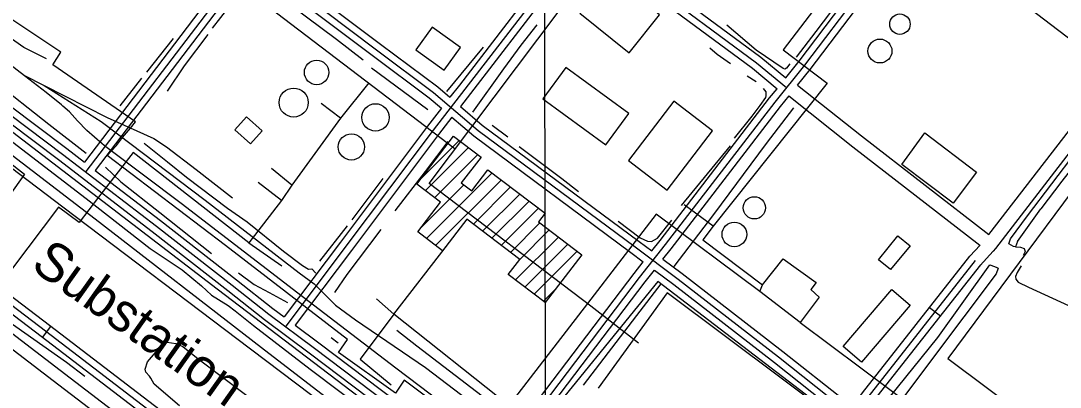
# Model space of a CAD drawing. Extents: x 3324104 to 3361979, y 612876 to 638273.
# Drawn here: x 3353376 to 3355626, y 633414 to 634208 of the extents above; entities that cross this region are included whole.
import ezdxf

# ---------------------------------------------------------------- set-up
doc = ezdxf.new("R2010")
doc.units = 0
for name, color, linetype in [('V-BLDG-OTLN', 7, 'Continuous'), ('V-DOMW-TANK', 7, 'Continuous'), ('V-GRID-MAJR', 7, 'Continuous'), ('V-RAIL-TRAK', 7, 'Continuous'), ('V-ROAD-CNTR', 7, 'Continuous'), ('V-SITE-OTLN', 7, 'Continuous'), ('V-SITE-OTLN-IDEN', 7, 'Continuous'), ('V-TOPO-SHOR', 7, 'Continuous'), ('V-UTIL-LINE', 7, 'Continuous')]:
    doc.layers.add(name, color=color, linetype=linetype)

msp = doc.modelspace()

# ---------------------------------------------------------------- linework, layer by layer
at = {"layer": 'V-BLDG-OTLN'}
for p, q in [((3354242.89947667, 633866.419240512), (3354325.0333124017, 633948.5530762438)), ((3354251.89945867, 633840.0632932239), (3354345.095272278, 633933.2601068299)), ((3354271.961418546, 633824.7703238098), (3354365.158232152, 633917.9671374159)), ((3354254.0074544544, 633736.1055011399), (3354396.202170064, 633878.3002167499)), ((3354242.7454769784, 633760.1994529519), (3354334.8252928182, 633852.2792687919)), ((3354274.0684143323, 633720.811531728), (3354416.26412994, 633863.007247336)), ((3354355.7272510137, 633767.1154391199), (3354436.326089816, 633847.714277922)), ((3354375.790210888, 633751.8224697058), (3354456.3880496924, 633832.4203085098)), ((3354395.852170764, 633736.5295002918), (3354476.450009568, 633817.1273390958)), ((3354415.915130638, 633721.237530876), (3354496.5119694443, 633801.8333696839)), ((3354435.9770905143, 633705.9445614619), (3354499.897962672, 633769.8644336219)), ((3354446.998068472, 633646.2546808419), (3354540.0198824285, 633739.2764947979)), ((3354455.94905057, 633690.5605922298), (3354518.711925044, 633753.3234667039)), ((3354467.060028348, 633630.9607114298), (3354560.0808423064, 633723.9825253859)), ((3354487.120988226, 633615.666742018), (3354580.1418021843, 633708.687555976)), ((3354507.1829481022, 633600.373772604), (3354533.405895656, 633626.5967201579))]:
    msp.add_line(p, q, dxfattribs=at)
for points in [[(3354586.5087894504, 634224.4325244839), (3354692.716577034, 634138.5826961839), (3354758.9704445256, 634220.547532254), (3354726.67850911, 634246.6494800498), (3354710.354541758, 634226.4545204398), (3354636.43868959, 634286.202400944)], [(3354231.018500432, 634144.7856837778), (3354292.5573773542, 634100.3837725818), (3354328.1203062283, 634149.671674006), (3354266.581429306, 634194.073585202)], [(3354692.0065784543, 634006.9889593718), (3354555.704851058, 634106.506760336), (3354506.204950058, 634038.7098959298), (3354642.506677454, 633939.192094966)], [(3354789.6713831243, 634033.366906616), (3354691.5335794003, 633905.258162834), (3354775.4344115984, 633840.98529138), (3354873.5732153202, 633969.0930351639)], [(3353864.7962328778, 634000.0049733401), (3353898.827164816, 633969.5720342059), (3353873.372215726, 633941.1080911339), (3353839.341283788, 633971.5420302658)], [(3355333.213, 633965.319), (3355444.8910000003, 633879.926), (3355394.647, 633812.77), (3355282.9620000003, 633896.7440000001)], [(3354456.0400503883, 633690.6515920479), (3354341.6012792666, 633777.883417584), (3354289.265383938, 633709.2265548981), (3354235.268491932, 633750.39047257), (3354284.61439324, 633815.124343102), (3354233.5004954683, 633854.089265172), (3354312.686337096, 633957.9650574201), (3354372.2832179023, 633912.53514828), (3354329.4663035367, 633856.363260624), (3354352.1622581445, 633839.0652952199), (3354387.2651879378, 633885.1132031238), (3354511.1399401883, 633790.6823919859), (3354496.971968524, 633772.0954291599), (3354590.1627821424, 633701.048571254), (3354511.124940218, 633597.3687786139), (3354431.311099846, 633658.2126569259)], [(3355232.323497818, 633690.158593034), (3355274.7144130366, 633741.798489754), (3355300.906360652, 633720.2975327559), (3355258.515445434, 633668.6576360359)], [(3355156.3836496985, 633502.3249687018), (3355261.846438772, 633625.56572222), (3355301.46235954, 633591.664790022), (3355195.999570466, 633468.424036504)]]:
    msp.add_lwpolyline(points, close=True, dxfattribs=at)
at = {"layer": 'V-DOMW-TANK'}
for centre, radius in [((3355279.0424043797, 634200.431572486), 22.136075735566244), ((3355235.8134908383, 634142.1696890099), 25.88489908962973), ((3354016.461929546, 634095.8497816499), 26.518120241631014), ((3353966.7360289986, 634030.5609122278), 31.449801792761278), ((3354143.8516747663, 633998.4999763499), 29.608969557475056), ((3354091.655779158, 633934.5241043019), 28.394865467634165), ((3354963.9790345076, 633802.628368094), 24.055551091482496), ((3354920.733121, 633744.9434834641), 26.720395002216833)]:
    msp.add_circle(centre, radius, dxfattribs=at)
at = {"layer": 'V-GRID-MAJR'}
msp.add_spline([(3354542.616, 618302.879), (3354530.278, 624362.207), (3354517.935, 630423.471), (3354505.593, 636484.758), (3354505.589, 636486.671)], degree=3, dxfattribs=at)
at = {"layer": 'V-RAIL-TRAK'}
for points in [[(3355824.3854434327, 634031.6344997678), (3355686.1738913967, 634137.7885225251), (3355480.9511141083, 634295.2301773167), (3355259.159114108, 634467.1391773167), (3355022.1207848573, 634648.9039759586), (3354854.770784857, 634777.0059759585), (3354747.4785265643, 634863.6636388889)], [(3354994.8000000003, 632277.343), (3354794.9390000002, 632430.505), (3354624.3740000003, 632561.778), (3354457.47, 632688.731), (3354410.4620000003, 632724.4890000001), (3354061.745, 632990.547), (3353708.9080000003, 633260.785), (3353584.803, 633355.677), (3353460.9620000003, 633450.366), (3353377.392, 633514.268), (3353092.648, 633732.826), (3352746.663, 633994.024), (3352512.14, 634175.561)], [(3352502.281, 634151.4230000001), (3352718.933, 633985.234), (3353086.217, 633704.517), (3353445.93, 633428.696), (3353715.359, 633222.774), (3353877.179, 633099.0970000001), (3354311.872, 632767.399), (3354334.588, 632752.709), (3354370.41, 632733.081), (3354457.47, 632688.731)], [(3354416.676, 633282.131), (3354188.215, 633455.425), (3353997.444, 633601.005), (3353984.9990000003, 633610.501), (3353723.356, 633812.084), (3353562.793, 633932.774), (3353552.002, 633940.885), (3353518.825, 633969.843), (3353498.943, 633990.6900000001), (3353481.721, 634010.183), (3353467.123, 634022.977), (3353464.073, 634025.5), (3353431.279, 634052.621), (3353384.123, 634088.359), (3353294.472, 634157.131)], [(3353382.424, 634089.664), (3353426.4020000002, 634067.435), (3353563.399, 633998.1900000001), (3353599.737, 633981.593), (3353627.295, 633969.008), (3353663.9050000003, 633952.712), (3353691.819, 633934.478), (3353755.575, 633885.931), (3353834.591, 633823.915)], [(3353426.4020000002, 634067.435), (3353550.046, 633989.735), (3353585.184, 633963.109), (3353775.187, 633819.137), (3353978.3880000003, 633662.058), (3354010.932, 633637.779), (3354020.732, 633628.386), (3354022.87, 633626.338), (3354057.346, 633592.028), (3354100.518, 633559.66), (3354252.0270000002, 633457.049), (3354436.648, 633316.13), (3354461.312, 633298.3470000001), (3354544.2660000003, 633238.5480000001), (3354564.187, 633223.042), (3354595.348, 633192.095), (3354655.018, 633132.893), (3354758.501, 633037.979), (3354838.068, 632959.931)], [(3354564.187, 633223.042), (3354499.233, 633290.296), (3354472.838, 633314.373), (3354440.191, 633344.153), (3354375.116, 633394.712), (3354233.661, 633502.5920000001), (3354189.8370000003, 633536.97)]]:
    msp.add_lwpolyline(points, dxfattribs=at)
at = {"layer": 'V-ROAD-CNTR'}
for p, q in [((3355343.1362761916, 633586.8577996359), (3355366.7352289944, 633568.3358366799)), ((3353422.7371169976, 633521.851929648), (3353440.9710805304, 633545.674882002))]:
    msp.add_line(p, q, dxfattribs=at)
for points in [[(3354182.121598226, 635746.1754809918), (3354018.760924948, 635537.3738985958), (3353982.41499764, 635481.0590112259), (3353715.4525315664, 635137.384698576), (3353649.706663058, 635051.1208711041), (3353421.915118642, 634750.8874715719), (3353365.78123091, 634675.6806219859), (3353063.8368348, 634284.0654052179), (3353055.92685062, 634262.7614478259), (3353056.6008492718, 634240.7944917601), (3353063.735835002, 634227.010519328), (3353091.9487785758, 634201.375570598), (3353466.5300294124, 633919.044135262), (3353669.547623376, 633763.143447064), (3353833.526295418, 633634.9757033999), (3353912.8701367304, 633572.257828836), (3354012.1179382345, 633498.229976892), (3354351.653259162, 633241.672490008), (3354431.0831003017, 633183.7016059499)], [(3354917.5051274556, 635717.3555386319), (3354668.8916246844, 635401.78716977), (3354512.4139376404, 635194.9325834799), (3354439.7530829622, 635096.420780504), (3354190.9995804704, 634777.8394176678), (3354117.5367273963, 634667.7306378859), (3353901.947158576, 634388.4701964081), (3353826.343309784, 634287.785397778), (3353516.7949288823, 633881.1582110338)], [(3353157.175648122, 635499.8729735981), (3353361.4352396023, 635334.13230508), (3353496.1649701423, 635235.156503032), (3353653.2386559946, 635113.25774683), (3353743.9004746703, 635047.529878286), (3353963.8420347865, 634886.9411994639), (3354117.5197274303, 634758.8044557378), (3354217.67952711, 634681.4496104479), (3354563.3308358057, 634421.7231299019), (3354647.9136666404, 634354.1892649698), (3354968.927024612, 634116.7357398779), (3355033.3788957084, 634063.260846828)], [(3354385.4241916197, 633216.154541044), (3354715.5335314, 633651.388670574), (3354771.896418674, 633722.899527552), (3355008.8109448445, 634031.2819107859), (3355072.8958166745, 634111.3617506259), (3355314.1163342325, 634430.291112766), (3355383.1521961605, 634526.260920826), (3355497.399967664, 634672.4536284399), (3355562.5108374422, 634771.8904295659), (3355642.2276780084, 634881.8442096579), (3355704.899552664, 634943.827085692), (3355851.978258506, 635128.869715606)], [(3352892.758176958, 635096.3707806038), (3352992.815976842, 635041.151891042), (3353182.5515973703, 634895.7211819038), (3353354.5072534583, 634748.9354754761), (3353438.82608482, 634686.254600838), (3353843.7952748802, 634371.5262302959), (3353920.754120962, 634314.868343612), (3354145.726671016, 634144.94468346), (3354269.488423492, 634052.6908679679), (3354365.761230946, 633970.008033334), (3354705.6285512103, 633717.741537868), (3354798.8313648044, 633648.3896765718), (3355016.481929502, 633479.5140143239), (3355149.9176626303, 633373.670226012), (3355228.120506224, 633317.9763373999), (3355464.206034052, 633129.06671522), (3355577.790806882, 633036.615900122)], [(3354918.7771249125, 634809.9303534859), (3354629.5387033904, 634443.890085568), (3354559.5568433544, 634348.5852761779), (3354337.55928735, 634059.4078545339), (3354268.538425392, 633970.497032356), (3354079.862802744, 633719.2585348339), (3353948.3830657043, 633544.18588498)], [(3353375.9132106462, 634714.3325446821), (3353353.8302548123, 634684.746603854), (3353050.567861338, 634291.4213905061), (3353040.843880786, 634265.2334428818), (3353041.712879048, 634236.926499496), (3353051.6538591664, 634217.721537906), (3353082.3707977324, 634189.8115937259), (3353457.448047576, 633907.106159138), (3353660.3606417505, 633751.2854707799), (3353824.256313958, 633623.1827269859), (3353903.733155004, 633560.3598526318), (3354003.1119562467, 633486.2340008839), (3354342.70927705, 633229.6295140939), (3354422.240117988, 633171.5856301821)], [(3353399.9891624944, 634696.434580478), (3353377.7322070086, 634666.6146401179), (3353077.105808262, 634276.70941993), (3353071.0098204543, 634260.28945277), (3353071.4888194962, 634244.6624840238), (3353075.8178108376, 634236.2995007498), (3353101.5267594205, 634212.9395474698), (3353475.6120112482, 633930.9821113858), (3353513.6419351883, 633901.779169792)], [(3355031.82289882, 634084.042805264), (3355061.055840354, 634120.5737322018), (3355302.044358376, 634439.1960949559), (3355329.684303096, 634477.6200181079)], [(3355057.566744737, 634068.2000049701), (3355084.735792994, 634102.14976905), (3355326.188310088, 634421.3861305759), (3355353.5982552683, 634459.4910543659)], [(3354574.189814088, 634393.858185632), (3354547.560867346, 634357.592258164), (3354325.685311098, 634068.5738362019), (3354305.0173524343, 634041.9498894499)], [(3354615.424731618, 634399.3241747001), (3354657.056648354, 634366.08424118), (3354978.1830061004, 634128.546716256), (3355031.82289882, 634084.042805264)], [(3354597.654767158, 634375.1242230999), (3354571.5528193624, 634339.5782941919), (3354349.433263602, 634050.2418728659), (3354327.803306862, 634022.3799285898)], [(3354597.654767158, 634375.1242230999), (3354638.7706849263, 634342.2942887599), (3354959.671043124, 634104.9247635), (3355013.075936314, 634060.615852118)], [(3353851.963258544, 634346.885279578), (3353814.378333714, 634296.8313796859), (3353513.6419351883, 633901.779169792)], [(3353894.1381741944, 634353.0892671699), (3353929.7211030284, 634326.893319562), (3354154.7296530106, 634156.9426594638), (3354278.8684047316, 634064.4078445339), (3354305.0173524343, 634041.9498894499)], [(3352388.9351846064, 634329.322314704), (3353429.22110403, 633535.778901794), (3354648.537665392, 632602.4947683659), (3355421.130120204, 632013.43894648), (3355932.4250976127, 631620.2727328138), (3356439.934082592, 631233.5865061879), (3356483.6699951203, 631203.683565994), (3356514.333933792, 631181.1316110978), (3356555.5778513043, 631160.7566518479), (3356591.2157800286, 631142.0616892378), (3356623.8377147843, 631131.1427110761), (3356662.57463731, 631117.0557392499), (3356708.263545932, 631110.2407528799), (3356754.1444541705, 631104.7047639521), (3356798.027366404, 631100.149773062), (3356827.982306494, 631100.7207719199), (3356869.341223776, 631103.031767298), (3356920.8921206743, 631112.5977481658)], [(3356918.1551261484, 631127.3457186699), (3356867.547227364, 631117.9547374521), (3356827.420307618, 631115.712741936), (3356798.661365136, 631115.164743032), (3356755.8174508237, 631119.611734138), (3356710.2685419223, 631125.107723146), (3356666.2816298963, 631131.6687100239), (3356628.782704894, 631145.30568275), (3356597.117768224, 631155.9036615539), (3356562.3848376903, 631174.1246251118), (3356522.1589181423, 631193.996585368), (3356492.3489777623, 631215.9205415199), (3356448.7180650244, 631245.7514818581), (3355941.5420793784, 631632.183708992), (3355430.249101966, 632025.3489226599), (3354657.64364718, 632614.4147445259), (3353438.3280858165, 633547.697877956), (3352398.0321664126, 634341.2482908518)], [(3353876.124210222, 634329.0993151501), (3353838.3082858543, 634278.7394158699), (3353537.4358876, 633883.507206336)], [(3353876.124210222, 634329.0993151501), (3353911.787138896, 634302.8433676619), (3354136.723689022, 634132.9467074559), (3354260.108442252, 634040.973891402), (3354286.5983892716, 634018.2229369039)], [(3354781.546399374, 632482.2200089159), (3354639.431683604, 632590.5747922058), (3353420.114122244, 633523.859925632), (3352379.8382027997, 634317.3963385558)], [(3355799.212888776, 634121.5072134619), (3355668.869269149, 633952.5124213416), (3355485.797764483, 633714.5395646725), (3355481.235984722, 633708.6103475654), (3355452.5515426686, 633677.4176287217)], [(3355775.457803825, 634139.8292204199), (3355645.102730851, 633970.8195786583), (3355470.965055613, 633744.4597194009)], [(3354742.0864782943, 633709.31055473), (3354760.0584423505, 633732.1115091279), (3354997.006968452, 634040.5378922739), (3355013.075936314, 634060.615852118)], [(3355057.6289575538, 634068.3321042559), (3355195.705558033, 633958.3452185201), (3355471.2003837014, 633744.7656200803)], [(3354766.164430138, 633691.393590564), (3354783.7343949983, 633713.6875459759), (3355020.614921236, 634022.0259292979), (3355038.9807783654, 634044.9754456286)], [(3355038.937306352, 634044.866764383), (3355177.168441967, 633934.7567814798), (3355452.29705448, 633721.4610927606)], [(3354286.5983892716, 634018.2229369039), (3354256.616449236, 633979.6000141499), (3354067.868826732, 633728.2665168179), (3353946.13007021, 633566.1638410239)], [(3354327.803306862, 634022.3799285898), (3354375.1292122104, 633981.7350098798), (3354714.575533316, 633729.7805137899), (3354742.0864782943, 633709.31055473)], [(3354309.3853436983, 633998.652976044), (3354280.4604015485, 633961.3940505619), (3354091.8567787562, 633710.2505528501), (3353970.177022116, 633548.2268768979)], [(3354309.3853436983, 633998.652976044), (3354356.393249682, 633958.2810567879), (3354696.681569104, 633705.7025619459), (3354723.509515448, 633685.7396018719)], [(3353537.4358876, 633883.507206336), (3353678.7346050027, 633775.001423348), (3353842.7962768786, 633646.7686798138), (3353922.007118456, 633584.1558050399), (3353946.13007021, 633566.1638410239)], [(3355452.737319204, 633721.9398559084), (3355430.469076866, 633697.7243937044)], [(3354766.164430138, 633691.393590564), (3354807.907346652, 633660.333652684), (3355025.740910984, 633491.3159907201), (3355158.9356445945, 633385.6632020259), (3355176.8076088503, 633372.9352274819)], [(3355176.8076088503, 633372.9352274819), (3355197.8965666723, 633401.809169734), (3355430.2641019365, 633697.867577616)], [(3354382.796196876, 633237.512498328), (3354703.666555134, 633660.564652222), (3354723.509515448, 633685.7396018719)], [(3354407.0331484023, 633219.823533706), (3354727.400507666, 633642.212688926), (3354747.586467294, 633667.8236377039)], [(3354747.586467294, 633667.8236377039), (3354789.755382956, 633636.44570046), (3355007.22294802, 633467.7120379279), (3355140.899680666, 633361.6772499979), (3355159.1116442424, 633348.7052759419)], [(3355442.0640783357, 633688.606596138), (3355209.856542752, 633392.7521878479), (3355024.054914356, 633138.360696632)], [(3355201.246559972, 633355.53126229), (3355221.8165188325, 633383.6952059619), (3355453.864054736, 633679.3456146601)], [(3353970.177022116, 633548.2268768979), (3354021.1239202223, 633510.2259528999), (3354360.597241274, 633253.7154659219), (3354382.796196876, 633237.512498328)]]:
    msp.add_lwpolyline(points, dxfattribs=at)
at = {"layer": 'V-SITE-OTLN'}
for points in [[(3352559.625, 634494.721), (3353467.182, 633804.738), (3353873.37, 633496.9890000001), (3354233.14, 633224.59), (3354687.045, 632870.501), (3355006.928, 632632.759), (3355121.593, 632542.686), (3355618.557, 632162.887)], [(3354440.332, 633253.359), (3354205.615, 633428.964), (3354187.468, 633400.804), (3354063.904, 633489.344), (3354083.432, 633517.493), (3353819.2460000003, 633720.917), (3353563.278, 633916.001), (3353572.114, 633925.7660000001), (3353583.009, 633937.786), (3353595.926, 633954.971), (3353613.702, 633975.213), (3353624.153, 633988.939), (3353445.6410000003, 634112.382), (3353462.4020000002, 634139.86), (3353301.71, 634246.612)], [(3355806.447, 634046.514), (3355383.103, 633475.9890000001), (3355717.721, 633225.348)], [(3353094.951000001, 633884.8699999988), (3353199.148000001, 634019.1819999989), (3353384.330000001, 633875.1159999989), (3353287.578000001, 633739.5279999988), (3353206.816000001, 633799.4259999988), (3353174.160000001, 633762.4339999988), (3353098.2690000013, 633818.1989999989), (3353125.476000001, 633859.3059999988), (3353091.253000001, 633888.4599999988)], [(3355184.272, 633314.809), (3354754.694, 633642.958), (3354481.4930000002, 633306.478)]]:
    msp.add_lwpolyline(points, dxfattribs=at)
at = {"layer": 'V-TOPO-SHOR'}
for p, q in [((3353648.807, 634096.379), (3353706.772, 634169.4130000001)), ((3354117.127, 634122.21), (3354059.357, 634167.375)), ((3354376.953, 634150.919), (3354297.357, 634054.839)), ((3354257.251, 634015.006), (3354135.031, 634104.716)), ((3353591.512, 634023.337), (3353638.0300000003, 634083.767)), ((3354967.7460000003, 634075.534), (3354948.644, 634087.757)), ((3354396.327, 633981.621), (3354430.2600000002, 633956.496)), ((3354911.293, 633936.639), (3354805.87, 633807.341)), ((3354093.555, 633776.363), (3354160.307, 633866.1410000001)), ((3355533.8680000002, 633729.6950000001), (3355583.8000000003, 633800.117)), ((3354023.2490000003, 633687.322), (3354083.509, 633763.642)), ((3354047.968, 633521.692), (3354063.244, 633510.227))]:
    msp.add_line(p, q, dxfattribs=at)
for points in [[(3353431.502, 634125.497), (3353382.93, 634149.8910000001), (3353331.77, 634185.659), (3353219.526, 634269.953), (3353145.407, 634326.22)], [(3354059.357, 634167.375), (3353994.264, 634215.263), (3353923.2060000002, 634269.873), (3353892.654, 634292.803), (3353879.33, 634296.907), (3353872.631, 634294.283), (3353862.5470000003, 634285.008), (3353790.4080000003, 634191.373)], [(3355147.095, 634250.118), (3355096.864, 634184.386), (3355054.528, 634129.255)], [(3354493.156, 634199.115), (3354458.715, 634154.587), (3354420.674, 634103.692), (3354353.8880000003, 634009.65)], [(3355040.915, 634114.43), (3355033.74, 634105.243), (3355030.171, 634103.135), (3355026.628, 634104.583), (3354967.924, 634144.103), (3354904.35, 634197.8740000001)], [(3353780.9620000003, 634178.088), (3353729.715, 634110.344), (3353692.583, 634055.1900000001)], [(3354912.591, 634114.317), (3354883.595, 634134.431), (3354867.349, 634148.052)], [(3353241.216, 634130.892), (3353315.63, 634078.928), (3353437.144, 633983.88), (3353517.491, 633921.189)], [(3354920.6580000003, 633953.629), (3354959.384, 634000.9670000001), (3354976.611, 634024.295), (3354988.818, 634041.263), (3354989.555, 634044.812), (3354989.622, 634054.053), (3354983.988, 634061.2000000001)], [(3355533.8680000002, 633729.6950000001), (3355529.111, 633718.378), (3355525.111, 633719.074), (3355514.463, 633724.495), (3355518.549, 633735.149), (3355554.975, 633784.968), (3355660.832, 633923.767), (3355763.2970000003, 634055.245), (3355768.006, 634059.886), (3355773.357, 634061.18), (3355777.355, 634059.816), (3355780.679, 634057.7880000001), (3355782.667, 634055.7710000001), (3355778.606, 634048.456), (3355755.728, 634024.58), (3355712.566, 633966.7980000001), (3355629.651, 633860.554), (3355583.8000000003, 633800.117)], [(3355048.357, 634018.797), (3354989.512, 633941.755), (3354875.3850000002, 633788.356), (3354789.9790000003, 633675.259)], [(3353329.985, 633966.345), (3353517.258, 633822.737), (3353656.036, 633714.208), (3353725.1520000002, 633668.294), (3353766.968, 633633.263), (3353788.864, 633613.735), (3353824.757, 633590.769), (3353840.0330000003, 633579.304), (3353879.8710000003, 633547.628), (3354002.7260000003, 633453.237), (3354317.5300000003, 633215.872), (3354508.805, 633071.568), (3354554.619, 633035.1730000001), (3354682.791, 632937.406), (3354803.666, 632846.37), (3354793.571, 632835.757), (3354782.113, 632821.1510000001), (3354680.489, 632896.685), (3354306.612, 633183.899), (3353896.881, 633499.422), (3353536.964, 633777.849), (3353242.107, 634003.715)], [(3353643.4390000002, 633942.408), (3353693.609, 633902.241), (3353734.592, 633869.248), (3353823.6550000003, 633801.786), (3353866.085, 633772.336), (3353944.512, 633708.506), (3353985.511, 633677.647), (3353998.9560000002, 633669.729), (3354006.068, 633670.389), (3354014.531, 633661.087)], [(3354300.1180000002, 633946.074), (3354251.312, 633881.042), (3354186.0160000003, 633796.228)], [(3354454.986, 633935.705), (3354546.875, 633866.0920000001), (3354583.629, 633838.104)], [(3353559.156, 633890.547), (3353592.985, 633858.9130000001), (3353677.307, 633792.185), (3353788.853, 633703.89)], [(3354669.16, 633773.514), (3354716.517, 633737.631), (3354732.811, 633730.403), (3354741.335, 633729.629), (3354754.178, 633736.644), (3354785.025, 633775.511)], [(3354155.159, 633755.942), (3354081.951, 633658.392), (3354055.37, 633619.496)], [(3355529.111, 633718.378), (3355539.7660000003, 633717.587), (3355548.274, 633714.683), (3355550.361, 633708.2710000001), (3355546.0270000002, 633699.063)], [(3355258.0130000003, 633356.402), (3355247.875, 633339.78), (3355244.5270000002, 633338.469), (3355235.87, 633341.871), (3355231.204, 633343.241), (3355225.892, 633347.2880000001), (3355225.278, 633354.638), (3355255.594, 633391.1460000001), (3355361.396, 633521.931), (3355473.401, 633679.384), (3355476.065, 633678.6950000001), (3355487.3850000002, 633673.938), (3355492.044, 633671.9), (3355487.276, 633659.248), (3355417.146, 633566.2660000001), (3355289.017, 633395.578)], [(3355541.603, 633677.061), (3355532.967, 633662.201), (3355529.35, 633653.698), (3355530.02, 633648.006), (3355534.947, 633641.573), (3355557.613, 633630.748), (3355678.744, 633575.134), (3355714.836, 633553.5480000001), (3355757.3170000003, 633531.207), (3355798.347, 633510.97)], [(3353847.316, 633662.06), (3353881.187, 633636.435), (3353913.785, 633619.502), (3353953.6950000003, 633597.84)], [(3354761.2770000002, 633637.799), (3354708.8910000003, 633569.238), (3354593.361, 633418.692)], [(3353313.556, 633581.336), (3353475.262, 633468.11), (3353514.466, 633438.084)], [(3353719.6040000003, 633373.963), (3353664.507, 633420.566), (3353657.4930000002, 633433.411), (3353654.683, 633437.6950000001), (3353646.927, 633446.28), (3353645.557, 633453.397), (3353650.646, 633468.997), (3353685.771, 633509.965), (3353692.8880000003, 633511.335), (3353711.347, 633508.355), (3353726.934, 633501.845), (3353760.147, 633475.305), (3354008.964, 633287.984)]]:
    msp.add_lwpolyline(points, dxfattribs=at)
at = {"layer": 'V-UTIL-LINE'}
for q in [(3354299.93, 633722.461), (3354146.322, 633605.236)]:
    msp.add_line((3354183.235, 633571.939), q, dxfattribs=at)
for points in [[(3356042.6920000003, 635808.587), (3356081.4990000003, 635577.697), (3356083.535, 635574.253), (3356117.4620000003, 635521.156), (3356118.795, 635515.657), (3355935.8680000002, 635277.465), (3355852.738, 635171.692), (3355853.403, 635168.941), (3355834.703, 635145.743), (3355831.952, 635145.078), (3355682.2830000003, 634949.881), (3355650.168, 634969.333), (3355639.068, 634952.941), (3355635.605, 634948.849), (3355488.6750000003, 634752.9450000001), (3355322.349, 634532.476), (3355026.46, 634144.806), (3355121.3310000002, 634072.735), (3354874.74, 633762.944), (3354811.938, 633809.387)], [(3354712.9760000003, 633509.5), (3354609.929, 633589.863), (3354259.7830000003, 633855.28), (3354589.6750000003, 634294.181), (3354459.35, 634398.7660000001), (3354532.828, 634498.432), (3354405.219, 634598.88), (3354382.63, 634607.281), (3354256.379, 634705.661), (3354220.035, 634710.044), (3354253.307, 634755.1), (3354141.404, 634844.452), (3354131.168, 634852.763), (3354343.833, 635121.62), (3354376.595, 635096.6730000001), (3354725.875, 635558.7660000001), (3354736.8680000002, 635560.7440000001), (3354880.978, 635449.966)], [(3354220.035, 634710.044), (3354086.577, 634525.238), (3354079.616, 634514.282), (3353880.9930000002, 634262.523), (3354316.416, 633930.63)], [(3352627.009, 634485.907), (3352647.5300000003, 634469.2440000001), (3352668.372, 634496.613), (3353110.38, 634156.236), (3353801.467, 633626.883), (3354284.555, 633258.681), (3354649.9760000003, 632983.539), (3354659.538, 632973.835), (3354733.151, 633066.876), (3354738.736, 633077.845), (3354967.285, 632904.16), (3355234.661, 633238.025)], [(3354129.489, 634073.112), (3354068.381, 633996.4940000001), (3354025.954, 634028.455)], [(3354068.381, 633996.4940000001), (3353962.737, 633851.393), (3353918.963, 633887.493)], [(3353869.626, 633726.844), (3353619.222, 633922.707), (3353544.201, 633825.549), (3353502.518, 633770.806), (3353457.35, 633804.164), (3353323.951, 633627.616), (3353026.952, 633849.966), (3352944.973, 633741.85)], [(3353962.737, 633851.393), (3353940.477, 633818.529), (3353889.844, 633857.431)], [(3353940.477, 633818.529), (3353869.626, 633726.844), (3353940.819, 633676.783)], [(3354975.7430000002, 633620.991), (3354751.284, 633789.142), (3354603.126, 633595.02), (3354432.251, 633374.711), (3354183.235, 633571.939), (3354110.967, 633474.76), (3354177.992, 633419.226)], [(3354874.74, 633762.944), (3354852.558, 633732.908), (3354981.566, 633635.88), (3355026.585, 633691.831), (3355097.589, 633640.525), (3355086.497, 633625.507), (3355104.22, 633608.906), (3355063.33, 633554.2980000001), (3355325.441, 633357.469), (3355234.661, 633238.025), (3355131.588, 633314.958), (3355133.671, 633318.377), (3355148.234, 633338.859), (3354775.539, 633618.167), (3354625.789, 633411.991)], [(3355063.33, 633554.2980000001), (3354975.7430000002, 633620.991), (3354981.566, 633635.88)]]:
    msp.add_lwpolyline(points, dxfattribs=at)

# ---------------------------------------------------------------- texts
at = {"layer": 'V-SITE-OTLN-IDEN'}
msp.add_text('Substation', height=82.9998320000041, rotation=324.6292773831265, dxfattribs=at).set_placement((3353394.8223431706, 633671.7512503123))

doc.saveas('drawing.dxf')
